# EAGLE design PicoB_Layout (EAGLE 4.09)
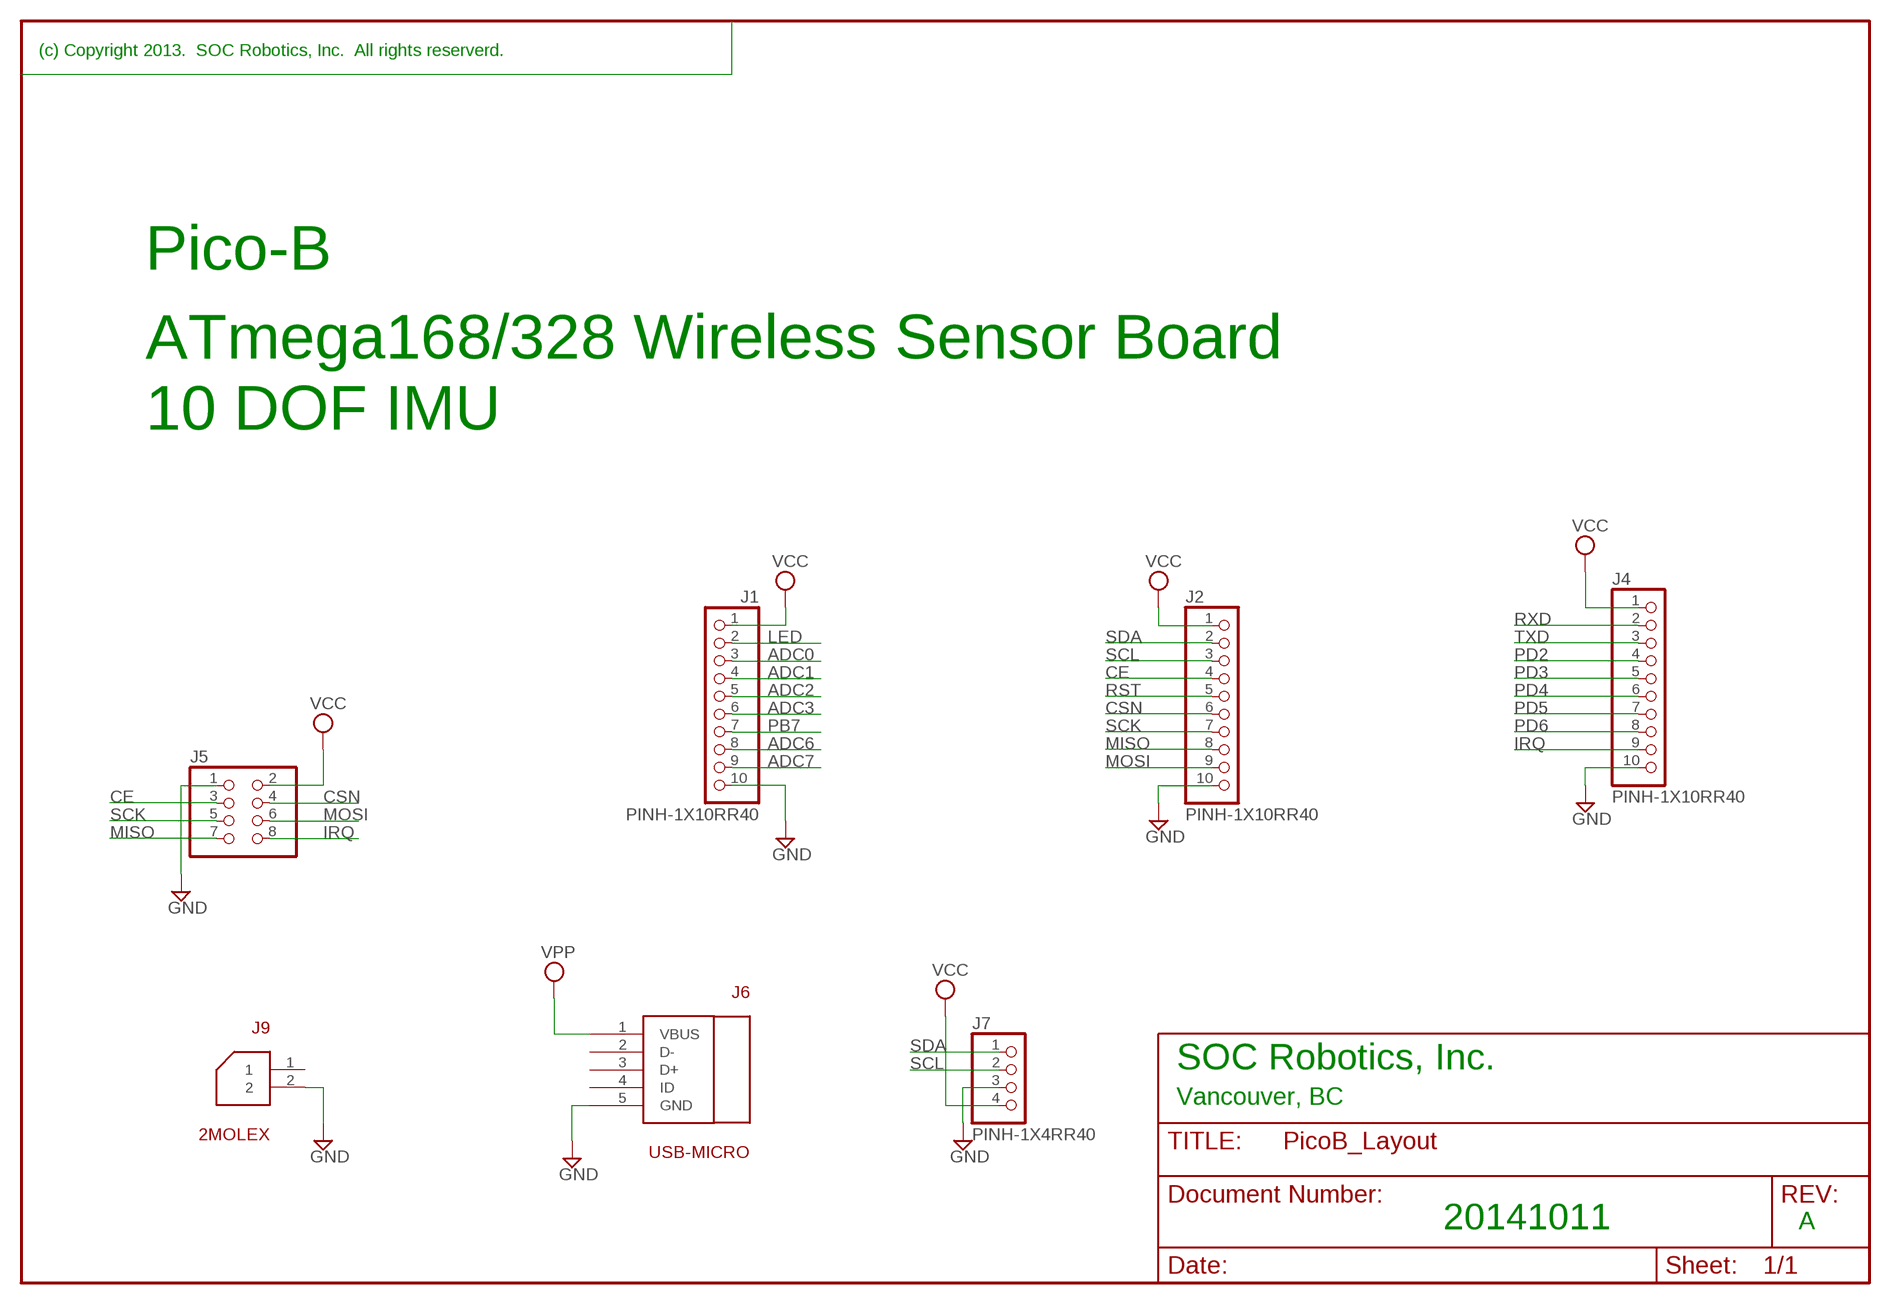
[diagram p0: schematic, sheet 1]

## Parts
J1  PINH-1X10RR40  [1X10ROUND]
J2  PINH-1X10RR40  [1X10ROUND]
J4  PINH-1X10RR40  [1X10ROUND]
J5  PINHD-2X4HEX  [2X04]
J6  USB-MICRO  [USB-MICRO]
J7  PINH-1X4RR40  [1X4ROUND]
J9  2MOLEX  PINH-1X2MOLEX  [1X2MOLEX]

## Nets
ADC0: J1.3
ADC1: J1.4
ADC2: J1.5
ADC3: J1.6
ADC6: J1.8
ADC7: J1.9
CE: J2.4 J5.3
CSN: J2.6 J5.4
GND: J1.10 J2.10 J4.10 J5.1 J6.5(GND) J7.3 J9.2
IRQ: J4.9 J5.8
LED: J1.2
MISO: J2.8 J5.7
MOSI: J2.9 J5.6
PB7: J1.7
PD2: J4.4
PD3: J4.5
PD4: J4.6
PD5: J4.7
PD6: J4.8
RST: J2.5
RXD: J4.2
SCK: J2.7 J5.5
SCL: J2.3 J7.2
SDA: J2.2 J7.1
TXD: J4.3
VCC: J1.1 J2.1 J4.1 J5.2 J7.4
VPP: J6.1(VBUS)
Unconnected: J6.2(D-) J6.3(D+) J6.4(ID) J9.1

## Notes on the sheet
- (c) Copyright 2013.  SOC Robotics, Inc.  All rights reserverd.
- Pico-B
- ATmega168/328 Wireless Sensor Board
- 10 DOF IMU
- SOC Robotics, Inc.
- Vancouver, BC
- 20141011 | A

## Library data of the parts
J1 J2 J4 = pinhead:PINH-1X10R
J5 = pinhead:PINHD-2X4: PIN HEADER
J6 = con-TI DSK 2:USB-MICRO: Micro USB
J7 = pinhead:PINH-1X4R: 1x4 Pin Head Round
J9 = pinhead:PINH-1X2MOLEX: 1x2 Molex 1.25mm thru-hole

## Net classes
1 VCC: width 0.305 mm, drill 0.203 mm, clearance 0.432 mm
2 GND: width 0.305 mm, drill 0.203 mm, clearance 0.432 mm
3 VTARGET: width 0.305 mm, drill 0.203 mm, clearance 0.432 mm
4 VIN: width 0.305 mm, drill 0.203 mm, clearance 0.432 mm

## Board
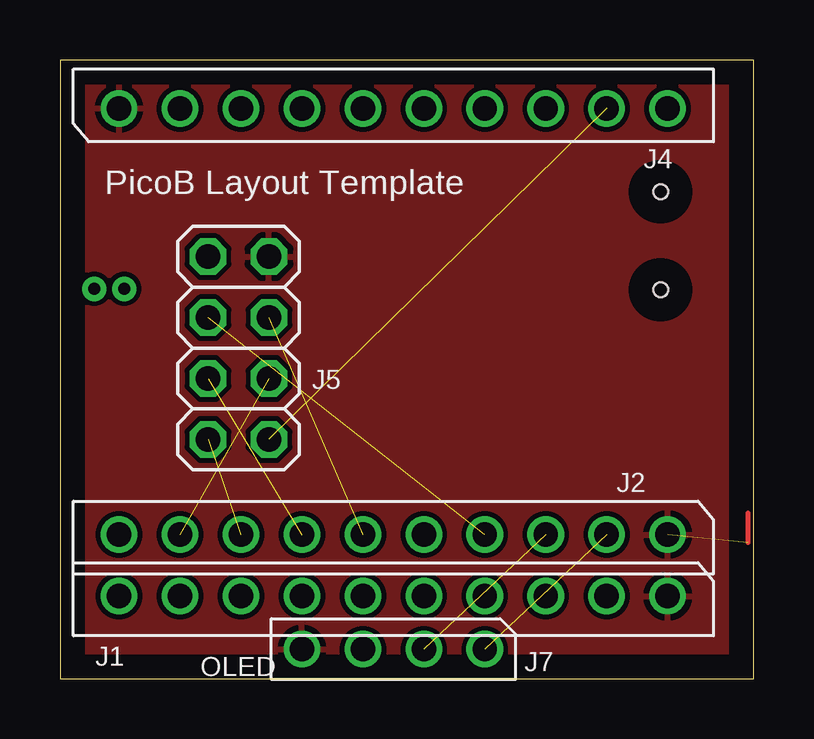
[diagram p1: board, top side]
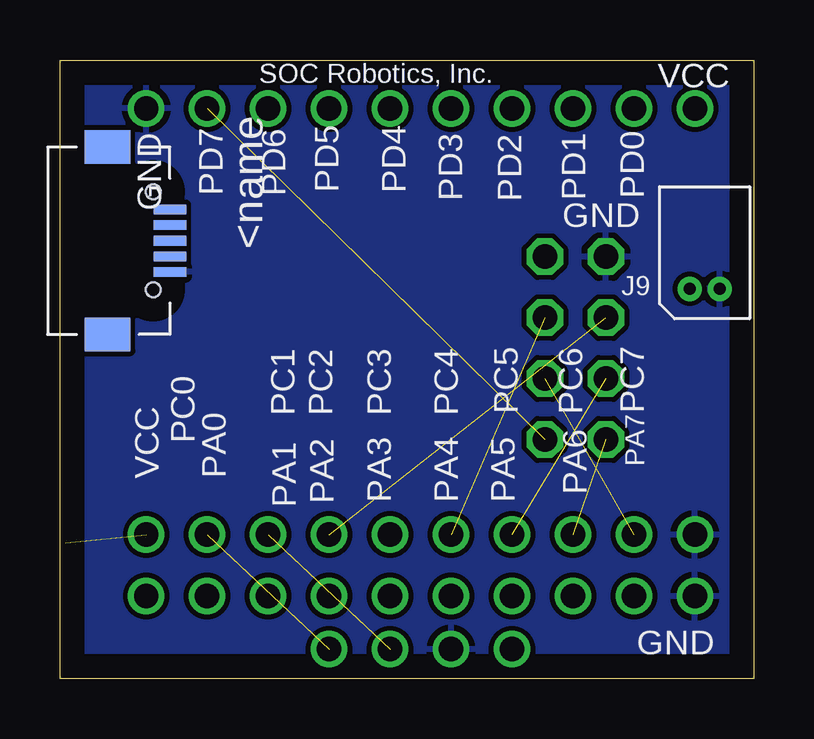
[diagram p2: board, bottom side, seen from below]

Size 28.91 x 25.78 mm. Coordinates in mm from the lower left corner, seen from the top.
Outline: 0,0 28.91,0 28.91,25.78 0,25.78 0,0
Copper layers used: Top, Bottom

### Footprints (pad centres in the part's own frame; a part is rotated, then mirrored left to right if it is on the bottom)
1X10ROUND = drill 1.016 round: 1 -11.43,0; 2 -8.89,0; 3 -6.35,0; 4 -3.81,0; 5 -1.27,0; 6 1.27,0; 7 3.81,0; 8 6.35,0; 9 8.89,0; 10 11.43,0
2X04 = drill 1.016 octagon: 1 -3.81,-1.27; 2 -3.81,1.27; 3 -1.27,-1.27; 4 -1.27,1.27; 5 1.27,-1.27; 6 1.27,1.27; 7 3.81,-1.27; 8 3.81,1.27
USB-MICRO = smd 0.4 x 1.35: 1 -1.3,0; 2 -0.65,0; 3 0,0; 4 0.65,0; 5 1.3,0 | smd 1.4 x 1.9: P$6 -3.9,-2.6; P$7 3.9,-2.6 | hole 0.61: -2.04,-0.7; 2.04,-0.7
1X4ROUND = drill 1.016 round: 1 -3.81,0; 2 -1.27,0; 3 1.27,0; 4 3.81,0
1X2MOLEX = drill 0.5 pad 0.9 round: 1 0.625,0; 2 -0.625,0

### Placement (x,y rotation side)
J1  13.89,3.44 180 top
J2  13.89,6.01 180 top
J4  13.89,23.76 0 top
J5  7.44,13.78 270 top
J6  24.33,18.25 270 bottom
J7  13.89,1.23 180 top
J9  2.05,16.24 180 bottom

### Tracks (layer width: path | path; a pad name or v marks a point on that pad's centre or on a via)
CE  (1 unrouted)
CSN  (1 unrouted)
GND
  pour Bottom: 0.1,25.67 28.8,25.67 28.77,0.11 0.12,0.11
IRQ  (1 unrouted)
MISO  (1 unrouted)
MOSI  (1 unrouted)
SCK  (1 unrouted)
SCL  (1 unrouted)
SDA  (1 unrouted)
VCC  (1 unrouted)
  Top 0.203: 28.67,5.68 28.67,6.9
  pour Top: 0.1,25.67 28.8,25.67 28.8,0.11 0.12,0.11

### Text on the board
tPlace: PicoB Layout Template | OLED
bPlace: VCC | SOC Robotics, Inc. | PD0 | PD1 | PD2 | PD3 | PD4 | PD5 | PD6 | PD7 | GND | GND | PC7 | PC6 | PC5 | PC4 | PC3 | PC2 | PC1 | PC0 | PA7 | PA0 | VCC | PA6 | PA5 | PA4 | PA3 | PA2 | PA1 | GND
_tplace: L1 | R3 | C3 | R2 | C4 | J4 | C1 | C10 | LD1 | U2 | C9 | C5 | Pico | B | C12 | C2 | U1 | D1 | R6 | L2 | U2 | C8 | C7 | J5 | R4 | U5 | R1 | J1 | R5 | C6 | J2 | R9 | R10 | OLED | J7 | J8
_bplace: VCC | SOC Robotics, Inc. | C11 | PD0 | PD1 | PD2 | PD3 | PD4 | PD5 | PD6 | PD7 | GND | U6 | GND | C14 | Pico | J9 | R7 | B | BC7 | BC6 | BC5 | BC4 | BC3 | PC1 | R8 | PC0 | U4 | PA7 | BC2 | PA0 | VCC | PA6 | PA5 | PA4 | PA3 | PA2 | PA1 | U3 | J10 | GND | OLED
